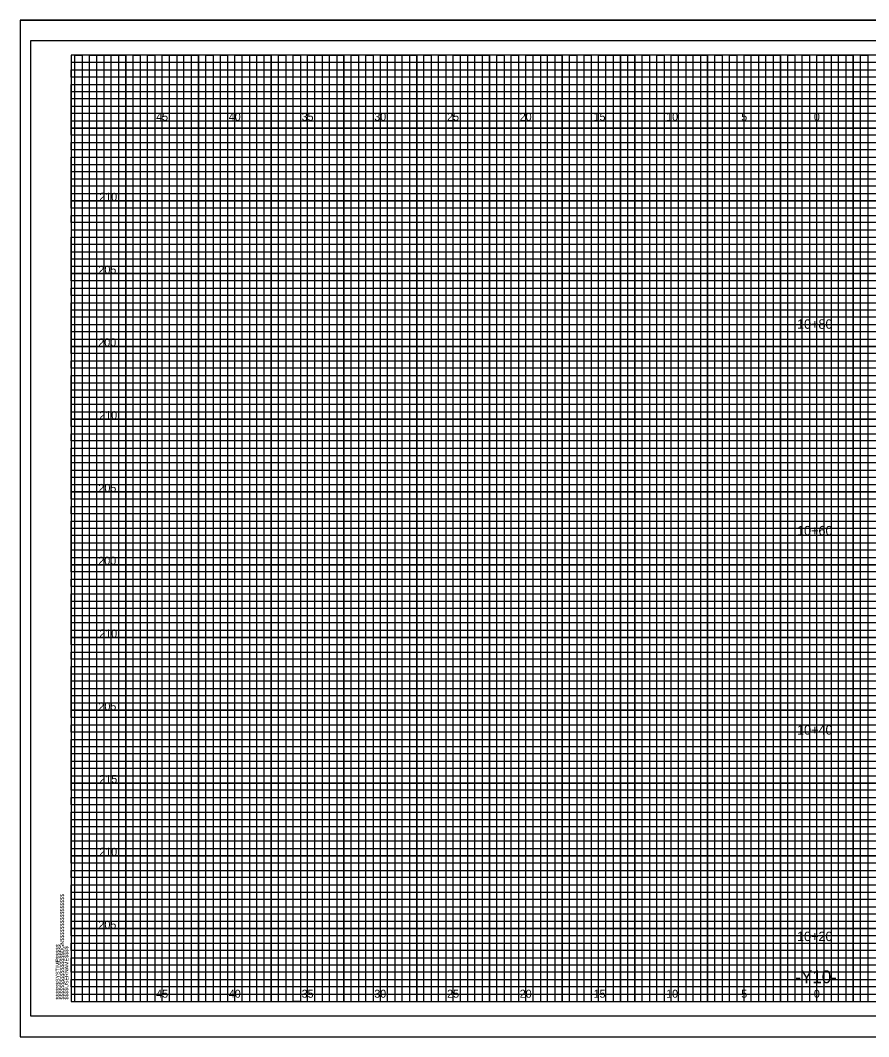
# Model space of a CAD drawing. Extents: x -4 to 103, y -2 to 67.
# Drawn here: x -3.5 to 54.8, y -2.4 to 67.4 of the extents above; entities that cross this region are included whole.
import ezdxf

# ---------------------------------------------------------------- set-up
doc = ezdxf.new("R2010")
doc.units = 0
for name, color, linetype in [('Old_Level_10', 7, 'Continuous'), ('Old_Level_16', 7, 'Continuous'), ('Old_Level_17', 7, 'Continuous'), ('Old_Level_3', 7, 'Continuous'), ('Old_Level_5', 7, 'Continuous'), ('Old_Level_8', 7, 'Continuous'), ('Prop Plan Preparation Sketches Hydraulic Ditch', 7, 'Continuous'), ('Prop XS Dump Level', 7, 'Continuous'), ('Prop XS Finish Grade', 7, 'Continuous'), ('Prop XS Finish Grade Pavement', 7, 'Continuous'), ('Prop XS Pvmt Edge Slope', 7, 'Continuous')]:
    doc.layers.add(name, color=color, linetype=linetype)

msp = doc.modelspace()

# ---------------------------------------------------------------- linework, layer by layer
at = {"layer": 'Old_Level_10'}
for p, q in [((1.25, 0), (1.25, 65)), ((3.75, 0), (3.75, 65)), ((6.25, 0), (6.25, 65)), ((8.75, 0), (8.75, 65)), ((11.25, 0), (11.25, 65)), ((13.75, 0), (13.75, 65)), ((16.25, 0), (16.25, 65)), ((18.75, 0), (18.75, 65)), ((21.25, 0), (21.25, 65)), ((23.75, 0), (23.75, 65)), ((26.25, 0), (26.25, 65)), ((28.75, 0), (28.75, 65)), ((31.25, 0), (31.25, 65)), ((33.75, 0), (33.75, 65)), ((36.25, 0), (36.25, 65)), ((38.75, 0), (38.75, 65)), ((41.25, 0), (41.25, 65)), ((43.75, 0), (43.75, 65)), ((46.25, 0), (46.25, 65)), ((48.75, 0), (48.75, 65)), ((51.25, 0), (51.25, 65)), ((53.75, 0), (53.75, 65)), ((0, 62.5), (74.25, 62.5)), ((0, 60), (102.5, 60)), ((0, 57.5), (102.5, 57.5)), ((0, 55), (102.5, 55)), ((0, 52.5), (102.5, 52.5)), ((0, 50), (102.5, 50)), ((0, 47.5), (102.5, 47.5)), ((0, 45), (102.5, 45)), ((0, 42.5), (102.5, 42.5)), ((0, 40), (102.5, 40)), ((0, 37.5), (102.5, 37.5)), ((0, 35), (102.5, 35)), ((0, 32.5), (102.5, 32.5)), ((0, 30), (102.5, 30)), ((0, 27.5), (102.5, 27.5)), ((0, 25), (102.5, 25)), ((0, 22.5), (102.5, 22.5)), ((0, 20), (102.5, 20)), ((0, 17.5), (102.5, 17.5)), ((0, 15), (102.5, 15)), ((0, 12.5), (102.5, 12.5)), ((0, 10), (102.5, 10)), ((0, 7.5), (102.5, 7.5)), ((0, 5), (102.5, 5)), ((0, 2.5), (102.5, 2.5))]:
    msp.add_line(p, q, dxfattribs=at)
at = {"layer": 'Old_Level_17'}
msp.add_lwpolyline([(103, 66), (-2.8, 66), (-2.8, -1), (103, -1)], close=True, dxfattribs=at)
at = {"layer": 'Old_Level_3'}
for p, q in [((-3.5, 67.4), (103.4, 67.4)), ((-3.5, 67.4), (-3.5, -2.425)), ((-3.5, -2.425), (103.4, -2.425))]:
    msp.add_line(p, q, dxfattribs=at)
at = {"layer": 'Old_Level_5'}
msp.add_lwpolyline([(103.4, 67.4), (-3.5, 67.4), (-3.5, -2.425), (103.4, -2.425)], close=True, dxfattribs=at)
at = {"layer": 'Old_Level_8'}
for points in [[(1.25, 0), (1.25, 65), (3.75, 65), (3.75, 0), (6.25, 0), (6.25, 65), (8.75, 65), (8.75, 0), (11.25, 0), (11.25, 65), (13.75, 65), (13.75, 0), (16.25, 0), (16.25, 65), (18.75, 65), (18.75, 0), (21.25, 0), (21.25, 65), (23.75, 65), (23.75, 0), (26.25, 0), (26.25, 65), (28.75, 65), (28.75, 0), (31.25, 0), (31.25, 65), (33.75, 65), (33.75, 0), (36.25, 0), (36.25, 65), (38.75, 65), (38.75, 0), (41.25, 0), (41.25, 65), (43.75, 65), (43.75, 0), (46.25, 0), (46.25, 65), (48.75, 65), (48.75, 0), (51.25, 0), (51.25, 65), (53.75, 65), (53.75, 0)], [(102.5, 60), (0, 60), (0, 62.5), (74.25, 62.5)], [(102.5, 55), (0, 55), (0, 57.5), (102.5, 57.5)], [(102.5, 50), (0, 50), (0, 52.5), (102.5, 52.5)], [(102.5, 45), (0, 45), (0, 47.5), (102.5, 47.5)], [(102.5, 40), (0, 40), (0, 42.5), (102.5, 42.5)], [(102.5, 35), (0, 35), (0, 37.5), (102.5, 37.5)], [(102.5, 30), (0, 30), (0, 32.5), (102.5, 32.5)], [(102.5, 25), (0, 25), (0, 27.5), (102.5, 27.5)], [(102.5, 20), (0, 20), (0, 22.5), (102.5, 22.5)], [(102.5, 15), (0, 15), (0, 17.5), (102.5, 17.5)], [(102.5, 10), (0, 10), (0, 12.5), (102.5, 12.5)], [(102.5, 5), (0, 5), (0, 7.5), (102.5, 7.5)], [(0, 2.5), (102.5, 2.5)]]:
    msp.add_lwpolyline(points, dxfattribs=at)
at = {"layer": 'Prop Plan Preparation Sketches Hydraulic Ditch'}
msp.add_lwpolyline([(102.5, 65), (0, 65), (0, 0), (102.5, 0)], close=True, dxfattribs=at)
at = {"layer": 'Prop XS Dump Level'}
for points in [[(0.25, 0), (0.25, 65), (0.75, 65), (0.75, 0), (1.75, 0), (1.75, 65), (2.25, 65), (2.25, 0), (2.75, 0), (2.75, 65), (3.25, 65), (3.25, 0), (4.25, 0), (4.25, 65), (4.75, 65), (4.75, 0), (5.25, 0), (5.25, 65), (5.75, 65), (5.75, 0), (6.75, 0), (6.75, 65), (7.25, 65), (7.25, 0), (7.75, 0), (7.75, 65), (8.25, 65), (8.25, 0), (9.25, 0), (9.25, 65), (9.75, 65), (9.75, 0), (10.25, 0), (10.25, 65), (10.75, 65), (10.75, 0), (11.75, 0), (11.75, 65), (12.25, 65), (12.25, 0), (12.75, 0), (12.75, 65), (13.25, 65), (13.25, 0), (14.25, 0), (14.25, 65), (14.75, 65), (14.75, 0), (15.75, 0), (15.25, 0), (15.25, 65), (15.75, 65), (15.75, 0), (16.75, 0), (16.75, 65), (17.25, 65), (17.25, 0), (17.75, 0), (17.75, 65), (18.25, 65), (18.25, 0), (19.25, 0), (19.25, 65), (19.75, 65), (19.75, 0), (20.25, 0), (20.25, 65), (20.75, 65), (20.75, 0), (21.75, 0), (21.75, 65), (22.25, 65), (22.25, 0), (22.75, 0), (22.75, 65), (23.25, 65), (23.25, 0), (24.25, 0), (24.25, 65), (24.75, 65), (24.75, 0), (25.25, 0), (25.25, 65), (25.75, 65), (25.75, 0), (26.75, 0), (26.75, 65), (27.25, 65), (27.25, 0), (27.75, 0), (27.75, 65), (28.25, 65), (28.25, 0), (29.25, 0), (29.25, 65), (29.75, 65), (29.75, 0), (30.25, 0), (30.25, 65), (30.75, 65), (30.75, 0)], [(30.75, 0), (31.75, 0), (31.75, 65), (32.25, 65), (32.25, 0), (32.75, 0), (32.75, 65), (33.25, 65), (33.25, 0), (34.25, 0), (34.25, 65), (34.75, 65), (34.75, 0), (35.25, 0), (35.25, 65), (35.75, 65), (35.75, 0), (36.75, 0), (36.75, 65), (37.25, 65), (37.25, 0), (37.75, 0), (37.75, 65), (37.75, 0)], [(38.25, 65), (38.25, 0), (39.25, 0), (39.25, 65), (39.75, 65), (39.75, 0), (40.25, 0), (40.25, 65), (40.75, 65), (40.75, 0), (41.75, 0), (41.75, 65), (42.25, 65), (42.25, 0), (42.75, 0), (42.75, 65), (43.25, 65), (43.25, 0), (43.75, 0), (44.25, 0), (44.25, 65), (44.75, 65), (44.75, 0), (45.25, 0), (45.25, 65), (45.75, 65), (45.75, 0), (46.75, 0), (46.75, 65), (47.25, 65), (47.25, 0), (47.75, 0), (47.75, 65), (48.25, 65), (48.25, 0), (49.25, 0), (49.25, 65), (49.75, 65), (49.75, 0), (50.25, 0), (50.25, 65), (50.75, 65), (50.75, 0), (51.75, 0), (51.75, 65), (52.25, 65), (52.25, 0), (52.75, 0), (52.75, 65), (53.25, 65), (53.25, 0), (54.25, 0), (54.25, 65), (54.75, 65), (54.75, 0), (55.25, 0)], [(0, 62), (0, 63), (74.25, 63), (74.25, 63.5), (0, 63.5), (0, 64), (74.25, 64), (74.25, 64.5), (0, 64.5)], [(102.5, 62), (0, 62)], [(102.5, 61), (0, 61), (0, 61.5), (102.5, 61.5)], [(102.5, 59.5), (0, 59.5), (0, 60.5), (102.5, 60.5)], [(102.5, 58.5), (0, 58.5), (0, 59), (102.5, 59)], [(102.5, 57), (0, 57), (0, 58), (102.5, 58)], [(102.5, 56), (0, 56), (0, 56.5), (102.5, 56.5)], [(102.5, 54.5), (0, 54.5), (0, 55.5), (102.5, 55.5)], [(102.5, 53.5), (0, 53.5), (0, 54), (102.5, 54)], [(0, 53), (102.5, 53)], [(102.5, 52), (0, 52)], [(102.5, 51), (0, 51), (0, 51.5), (102.5, 51.5)], [(102.5, 49.5), (0, 49.5), (0, 50.5), (102.5, 50.5)], [(102.5, 48.5), (0, 48.5), (0, 49), (102.5, 49)], [(102.5, 47), (0, 47), (0, 48), (102.5, 48)], [(102.5, 46), (0, 46), (0, 46.5), (102.5, 46.5)], [(102.5, 44.5), (0, 44.5), (0, 45.5), (102.5, 45.5)], [(102.5, 43.5), (0, 43.5), (0, 44), (102.5, 44)], [(102.5, 42), (0, 42), (0, 43), (102.5, 43)], [(102.5, 41), (0, 41), (0, 41.5), (102.5, 41.5)], [(102.5, 39.5), (0, 39.5), (0, 40.5), (102.5, 40.5)], [(102.5, 38.5), (0, 38.5), (0, 39), (102.5, 39)], [(102.5, 37), (0, 37), (0, 38), (102.5, 38)], [(102.5, 36), (0, 36), (0, 36.5), (102.5, 36.5)], [(102.5, 34.5), (0, 34.5), (0, 35.5), (102.5, 35.5)], [(102.5, 33.5), (0, 33.5), (0, 34), (102.5, 34)], [(102.5, 32), (0, 32), (0, 33), (102.5, 33)], [(102.5, 31), (0, 31), (0, 31.5)], [(0, 31.5), (102.5, 31.5)], [(102.5, 29.5), (0, 29.5), (0, 30.5), (102.5, 30.5)], [(102.5, 28.5), (0, 28.5), (0, 29), (102.5, 29)], [(102.5, 27), (0, 27), (0, 28), (102.5, 28)], [(102.5, 26), (0, 26), (0, 26.5), (102.5, 26.5)], [(102.5, 24.5), (0, 24.5), (0, 25.5), (102.5, 25.5)], [(102.5, 23.5), (0, 23.5), (0, 24), (102.5, 24)], [(102.5, 22), (0, 22), (0, 23), (102.5, 23)], [(102.5, 21), (0, 21), (0, 21.5), (102.5, 21.5)], [(102.5, 19.5), (0, 19.5), (0, 20.5), (102.5, 20.5)], [(102.5, 18.5), (0, 18.5), (0, 19), (102.5, 19)], [(102.5, 17), (0, 17), (0, 18), (102.5, 18)], [(102.5, 16), (0, 16), (0, 16.5), (102.5, 16.5)], [(102.5, 14.5), (0, 14.5), (0, 15.5), (102.5, 15.5)], [(102.5, 13.5), (0, 13.5), (0, 14), (102.5, 14)], [(102.5, 12), (0, 12), (0, 13), (102.5, 13)], [(102.5, 11), (0, 11), (0, 11.5), (102.5, 11.5)], [(102.5, 9.5), (0, 9.5), (0, 10.5), (102.5, 10.5)], [(102.5, 8.5), (0, 8.5), (0, 9), (102.5, 9)], [(102.5, 7), (0, 7), (0, 8), (102.5, 8)], [(102.5, 6), (0, 6), (0, 6.5), (102.5, 6.5)], [(102.5, 4.5), (0, 4.5), (0, 5.5), (102.5, 5.5)], [(102.5, 3.5), (0, 3.5), (0, 4), (102.5, 4)], [(102.5, 2), (0, 2), (0, 3), (102.5, 3)], [(102.5, 1), (0, 1), (0, 1.5), (102.5, 1.5)], [(0, 0.5), (102.5, 0.5)]]:
    msp.add_lwpolyline(points, dxfattribs=at)

# ---------------------------------------------------------------- texts
at = {"layer": 'Old_Level_16'}
for s, p in [('45', (5.8399, 60.5)), ('40', (10.8313, 60.5)), ('35', (15.8399, 60.5)), ('30', (20.8313, 60.5)), ('25', (25.8399, 60.5)), ('20', (30.8313, 60.5)), ('15', (35.9058, 60.5)), ('10', (40.8971, 60.5)), ('5', (46.0574, 60.5)), ('0', (51.0488, 60.5)), ('0', (51.0488, 60.5)), ('45', (5.8399, 0.25)), ('40', (10.8313, 0.25)), ('35', (15.8399, 0.25)), ('30', (20.8313, 0.25)), ('25', (25.8399, 0.25)), ('20', (30.8313, 0.25)), ('15', (35.9058, 0.25)), ('10', (40.8971, 0.25)), ('5', (46.0574, 0.25)), ('0', (51.0488, 0.25)), ('0', (51.0488, 0.25))]:
    msp.add_text(s, height=0.55, dxfattribs=at).set_placement(p)
at = {"layer": 'Old_Level_8'}
msp.add_text('040397', height=0.0025, rotation=90, dxfattribs=at).set_placement((-0.0007, 64.9864))
at = {"layer": 'Prop Plan Preparation Sketches Hydraulic Ditch'}
for s, p in [('$$$$$$$$$$$$$$$$DGN$$$$$$$$$$$$$$$$', (-0.5, 0.125)), ('$$$$$$SYSTIME$$$$$', (-0.7973, 0.1247)), ('$$$$USERNAME$$$$', (-0.2, 0.125))]:
    msp.add_text(s, height=0.2625, rotation=90, dxfattribs=at).set_placement(p)
at = {"layer": 'Prop XS Finish Grade'}
for s, p in [('10+80', (49.8934, 46.2075)), ('10+60', (49.8934, 32.0135)), ('10+40', (49.8934, 18.3267)), ('10+20', (49.8934, 4.1418))]:
    msp.add_text(s, height=0.65, dxfattribs=at).set_placement(p)
at = {"layer": 'Prop XS Finish Grade Pavement'}
for s, p in [('210', (1.9296, 55)), ('205', (1.8724, 50)), ('200', (1.8638, 45)), ('210', (1.9296, 40)), ('205', (1.8724, 35)), ('200', (1.8638, 30)), ('210', (1.9296, 25)), ('205', (1.8724, 20)), ('215', (1.9383, 15)), ('210', (1.9296, 10)), ('205', (1.8724, 5))]:
    msp.add_text(s, height=0.55, dxfattribs=at).set_placement(p)
at = {"layer": 'Prop XS Pvmt Edge Slope'}
msp.add_text('-Y10-', height=0.875, dxfattribs=at).set_placement((49.7731, 1.25))

doc.saveas('drawing.dxf')
